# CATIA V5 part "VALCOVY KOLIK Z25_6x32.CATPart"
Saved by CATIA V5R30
Part number: VALCOVY KOLIK Z25/6x32
Bounding box of the stored display mesh (mm): x -32 to -0.009, y -3 to 3, z -3 to 3
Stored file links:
  C:\Users\ondra\Desktop\PŘÍLOHA P III\CATIA\VALCOVY KOLIK Z25_6x32.CATPart
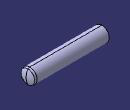
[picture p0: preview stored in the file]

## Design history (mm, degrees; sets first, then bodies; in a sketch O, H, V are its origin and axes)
Set1
  DatumSurface1 to DatumSurface8 "Z25/6x32"
  Join1: Elements (DatumSurface1; DatumSurface2; DatumSurface3; DatumSurface4; DatumSurface5; DatumSurface6; DatumSurface7; DatumSurface8)
Body1 (main body)
  CloseSurface1: CloseElement Join1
